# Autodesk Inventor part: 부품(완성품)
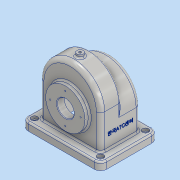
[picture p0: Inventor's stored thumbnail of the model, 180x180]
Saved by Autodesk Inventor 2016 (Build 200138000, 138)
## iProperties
Created: 2017-11
Part Number: 부품(완성품)
Material: 알루미늄 6061
Document SubType Name: Modeling
Designer: 605-17
Density: 2.7 g/cm^3
Appearance: 알루미늄 - 평지
Mass: 1073.21 g
Surface Area: 1187.53 cm^2
Volume: 397.487 cm^3
Author: 605-17
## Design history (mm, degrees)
sketch "스케치1"
  geometry: L1 (-43, -75)-(43, -75); L2 (55, -63)-(55, 63); L3 (43, 75)-(-43, 75); L4 (-55, 63)-(-55, -63); A1 r 12 centre (-43, 63) between (-43, 75) and (-55, 63); A2 r 12 centre (43, 63) between (55, 63) and (43, 75); A3 r 12 centre (43, -63) between (43, -75) and (55, -63); A4 r 12 centre (-43, -63) between (-55, -63) and (-43, -75); 3 further points
  constraints: 8 end point, 8 point on circle, 8 tangent, 4 centre point, 3 equal radius, 2 midpoint, 2 parallel, 1 horizontal, 1 horizontal alignment, 1 perpendicular, 1 vertical alignment
  dimensions: "d0" = 12 radius of A1; "d1" = 110 distance between parallel lines of L2 L4; "d2" = 150 distance between parallel lines of L1 L3
extrude "돌출1" new body sketch "스케치1" distance "d3" = 15; taper "d4" = 0 deg
sketch "스케치3"
  geometry: L1 (-75, 0)-(-63, 0) reference; L2 (-63, 0)-(63, 0) reference; L3 (63, 0)-(75, 0) reference; L4 (-58, 0)-(-58, 80); L5 (58, 80)-(58, 0); L6 (-58, 0)-(58, 0); A1 r 58 centre (0, 80) between (58, 80) and (-58, 80); 2 further points
  constraints: 6 end point, 2 point on circle, 2 point on line, 2 tangent, 1 centre point, 1 collinear, 1 midpoint, 1 perpendicular, 1 vertical, 1 vertical alignment
  dimensions: "d13" = 116 distance between parallel lines of L5 L4; "d14" = 80 distance from line of L2 A1.centre
extrude "돌출2" join sketch "스케치3" distance "d16" = 38; taper "d17" = 0 deg
sketch "스케치4"
  geometry: L1 (-63, 0)-(63, 0) reference; L2 (-58, 0)-(-58, 57); L3 (58, 57)-(58, 0); A1 r 58 centre (0, 57) between (58, 57) and (-58, 57); 2 further points
  constraints: 4 end point, 2 point on circle, 2 point on line, 2 tangent, 1 centre point, 1 midpoint, 1 perpendicular, 1 vertical, 1 vertical alignment
  dimensions: "d18" = 57 distance of A1.centre point (0, 0); "d19" = 58 radius of A1
extrude "돌출3" join sketch "스케치4" distance "d20" = 38; taper "d21" = 0 deg
node "작업 평면6"
sketch "스케치14"
  geometry: L1 (-38, 58)-(-38, -58) reference; C1 r 6 at (-19, 0); 1 further point
  constraints: 1 centre point, 1 horizontal alignment
  dimensions: "d88" = 12 diameter of C1; "d89" = 19 distance from line of C1.centre L1
extrude "돌출8" join sketch "스케치14" distance "d90" = 20; taper "d91" = 0 deg
node "작업 평면2"
node "작업 평면4"
sketch "스케치16"
  geometry: L1 (-17, -80)-(-17, -65) reference; L2 (-5, -80)-(81, -80) reference; L3 (0, 0)-(0, -65) reference; 2 further points
  constraints: 1 other
  dimensions: "d118" = 40 distance from line of L2 point (38, -40); "d119" = 38 distance from line of point (38, -40) L3
feature "엠보싱1" sketch "스케치16" dims "d0" = 12, "d1" = 110, "d2" = 150, "d120" = 0.5, "d121" = 0
sketch "스케치9"
  geometry: L1 (-53, 57)-(-53, 0); L2 (53, 57)-(53, 0); L3 (-63, 0)-(63, 0) reference; L4 (-58, 15)-(-58, 80) reference; L5 (58, 80)-(58, 15) reference; A1 r 58 centre (0, 57) between (58, 57) and (-58, 57) reference; A2 r 53 centre (0, 57) between (53, 57) and (-53, 57); 1 further point
  constraints: 4 end point, 2 point on circle, 2 point on line, 2 vertical, 1 centre point
  dimensions: "d41" = 5 radial gap between concentric circles of A2 A1; "d42" = 5 distance between parallel lines of L1 L4; "d43" = 5 distance between parallel lines of L2 L5
extrude "돌출6" cut sketch "스케치9" distance "d44" = 14; taper "d45" = 0 deg; dims "d46" = 25, "d47" = 0
sketch "스케치6"
  geometry: L1 (-63, 0)-(63, 0) reference; L2 (58, 57)-(58, 80) reference; L3 (-58, 80)-(-58, 57) reference; L4 (-58, 15)-(-58, 57) reference; L5 (-53, 0)-(-53, 80); L6 (-53, 57)-(-53, 80); L7 (53, 80)-(53, 0); A1 r 58 centre (0, 80) between (58, 80) and (-58, 80) reference; A2 r 53 centre (0, 80) between (53, 80) and (-53, 80); 1 further point
  constraints: 6 end point, 3 point on line, 2 point on circle, 1 centre point, 1 other
  dimensions: "d27" = 5 radial gap between concentric circles of A2 A1; "d28" = 5 distance between parallel lines of L7 L2
extrude "돌출4" cut sketch "스케치6" stored distance "d29" = 28; taper "d30" = 0 deg
sketch "스케치7"
  geometry: L1 (0, 53)-(0, -53) reference; C1 r 37.5 at (65, 0); 2 further points
  constraints: 1 centre point, 1 horizontal alignment, 1 midpoint
  dimensions: "d31" = 75 diameter of C1; "d32" = 65 distance of C1.centre point (0, 0)
extrude "돌출5" join sketch "스케치7" distance "d33" = 9; taper "d34" = 0 deg
sketch "스케치11"
  geometry: L1 (0, -53)-(0, 53) reference; C1 r 31 at (-65, 0); A1 r 58 centre (-57, 0) between (-57, 58) and (-57, -58) reference; 2 further points
  constraints: 1 centre point, 1 horizontal alignment, 1 midpoint
  dimensions: "d69" = 62 diameter of C1; "d70" = 65 distance of point (0, 0) C1.centre
extrude "돌출7" join sketch "스케치11" distance "d71" = 10; taper "d72" = 0 deg
hole "구멍1" diameter "d50" = 32; stored, may be unused: countersink angle "d54" = 90 deg, drill point angle "d56" = 0 deg; dims "d48" = 10, "d49" = 10, "d51" = 6, "d52" = 4, "d53" = 2, "d55" = 8
sketch "스케치10" dims "d57" = 58
  geometry: C1 r 37.5 at (0, 0) reference; 3 further points
  constraints: 2 vertical alignment, 1 coincident, 2 other
hole "구멍2" sketch "스케치10" at (0, 29) diameter "d58" = 2.459; stored, may be unused: countersink angle "d62" = 90 deg, drill point angle "d64" = 118 deg; dims "d59" = 6, "d60" = 4, "d61" = 2, "d63" = 8
sketch "스케치12" dims "d73" = 52
  geometry: C1 r 31 at (0, 0) reference; 3 further points
  constraints: 2 vertical alignment, 1 coincident, 2 other
hole "구멍3" sketch "스케치12" at (0, 26) diameter "d74" = 2.459; stored, may be unused: countersink angle "d78" = 90 deg, drill point angle "d80" = 118 deg; dims "d75" = 6, "d76" = 4, "d77" = 2, "d79" = 8
node "작업 평면5"
hole "구멍4" diameter "d94" = 4.459; stored, may be unused: countersink angle "d98" = 90 deg, drill point angle "d100" = 118 deg; dims "d92" = 10, "d93" = 10, "d95" = 40, "d96" = 4, "d97" = 2, "d99" = 50
sketch "스케치15"
  geometry: L1 (-43, 75)-(43, 75) reference; L2 (55, 63)-(55, -63) reference; L3 (43, -75)-(-43, -75) reference; L4 (-55, -63)-(-55, 63) reference; L5 (33, 53)-(-33, 53) reference; L6 (-33, 53)-(-33, -53) reference; L7 (-33, -53)-(33, -53) reference; L8 (33, -53)-(33, 53) reference; A1 r 12 centre (43, 63) between (55, 63) and (43, 75) reference; A2 r 12 centre (43, -63) between (43, -75) and (55, -63) reference; A3 r 12 centre (-43, -63) between (-55, -63) and (-43, -75) reference; A4 r 12 centre (-43, 63) between (-43, 75) and (-55, 63) reference; 5 further points
  constraints: 4 coincident
hole "구멍5" sketch "스케치15" at (43, 63), (-43, 63), (-43, -63), (43, -63) diameter "d101" = 5; stored, may be unused: countersink angle "d105" = 90 deg, drill point angle "d107" = 0 deg; dims "d102" = 40, "d103" = 12, "d104" = 5, "d106" = 50
fillet "모깎기2" dims "d109" = 8
fillet "모깎기3" dims "d110" = 3
fillet "모깎기4" dims "d111" = 3
chamfer "모따기1" distance "d112" = 1; stored, may be unused: second distance "d113" = 2, angle "d114" = 45 deg
chamfer "모따기2" distance "d115" = 1; stored, may be unused: second distance "d116" = 2, angle "d117" = 45 deg
fillet "모깎기5" dims "d122" = 3
node "솔리드1"
pattern_circular "원형 패턴1" dims angle "d66" = 360 deg
pattern_circular "원형 패턴2" dims angle "d82" = 360 deg
node "투영된 루프1"
other parameters: "d26" = -19, "d39" = 19, "d84" = 144, "d87" = 144
